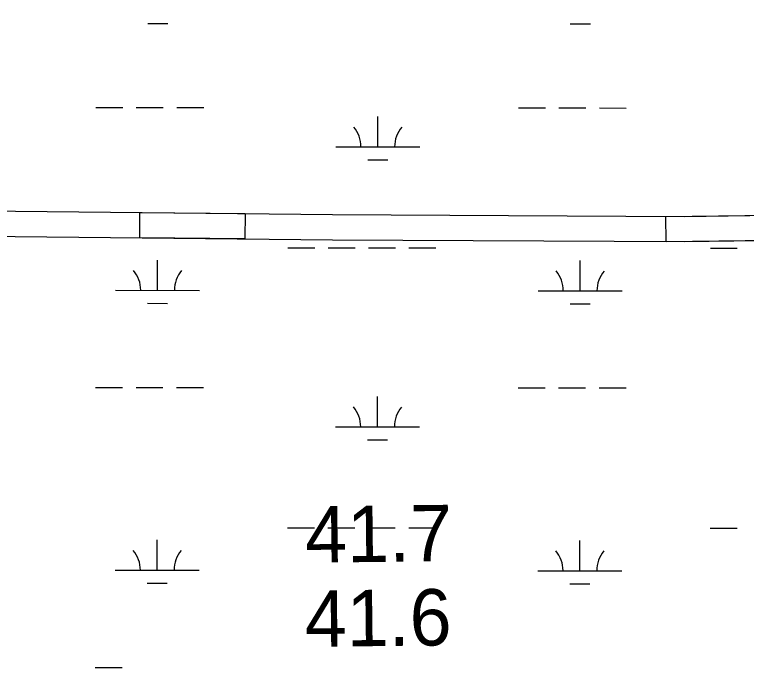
# Model space of a CAD drawing. Extents: x 3148686 to 3186545, y 916144 to 941516.
# Drawn here: x 3164337 to 3165206, y 933764 to 934539 of the extents above; entities that cross this region are included whole.
import ezdxf

# ---------------------------------------------------------------- set-up
doc = ezdxf.new("R2010")
doc.units = 0
for name, color, linetype in [('V-RIVR-RANG', 7, 'Continuous'), ('V-ROAD-CNTR', 7, 'Continuous'), ('V-WETL-SWMP', 7, 'Continuous')]:
    doc.layers.add(name, color=color, linetype=linetype)

msp = doc.modelspace()

# ---------------------------------------------------------------- linework, layer by layer
at = {"layer": 'V-ROAD-CNTR'}
for points in [[(3163359.71, 934289.29), (3163482.63, 934282.09), (3164073.39, 934278.51), (3164713.97, 934271.75), (3165132.24, 934269.66), (3165570.17, 934275.62), (3166245.62, 934279.09), (3166867.78, 934288.1), (3167164.82, 934288.69), (3167686.85, 934272.97), (3168000.91, 934271.8), (3168168.65, 934286.1), (3168244.17, 934320.97), (3168298.4, 934368), (3168350.14, 934433.57), (3168384.08, 934490.47), (3168443.51, 934622.25), (3168480.03, 934725.34), (3168496.65, 934826.01), (3168498.83, 934894.77), (3168492.36, 935008.72), (3168468.41, 935144.95), (3168439.08, 935248.42)], [(3163361.47, 934319.24), (3163483.6, 934312.08), (3164073.64, 934308.51), (3164714.2, 934301.75), (3165132.12, 934299.66), (3165235.77, 934301.07)]]:
    msp.add_lwpolyline(points, dxfattribs=at)
for points in [[(3164485.49, 934304.16), (3164610.48, 934302.84), (3164610.16, 934272.84), (3164485.17, 934274.16)], [(3165110.11, 934299.36), (3165235.1, 934301.06), (3165235.5, 934271.06), (3165110.52, 934269.36)]]:
    msp.add_lwpolyline(points, close=True, dxfattribs=at)
at = {"layer": 'V-WETL-SWMP'}
for p, q in [((3164494.63, 934528.97), (3164518.63, 934528.95)), ((3164996.54, 934528.44), (3165020.54, 934528.42)), ((3164433.12, 934429.04), (3164465.12, 934429)), ((3164481.12, 934428.99), (3164513.12, 934428.95)), ((3164529.12, 934428.94), (3164561.12, 934428.9)), ((3164935.03, 934428.51), (3164967.03, 934428.47)), ((3164983.03, 934428.46), (3165015.03, 934428.42)), ((3165031.03, 934428.41), (3165063.03, 934428.37)), ((3164767.91, 934382.25), (3164767.95, 934418.25)), ((3164717.91, 934382.31), (3164817.91, 934382.2)), ((3164755.9, 934366.84), (3164779.9, 934366.81)), ((3164660.94, 934262.3), (3164692.94, 934262.26)), ((3164708.94, 934262.25), (3164740.94, 934262.21)), ((3164756.94, 934262.19), (3164788.94, 934262.16)), ((3164804.94, 934262.14), (3164836.94, 934262.11)), ((3165162.85, 934261.77), (3165194.85, 934261.73)), ((3164506.3, 934211.72), (3164506.34, 934247.72)), ((3165008.21, 934211.19), (3165008.24, 934247.19)), ((3164456.3, 934211.77), (3164556.3, 934211.66)), ((3164958.21, 934211.24), (3165058.21, 934211.14)), ((3164494.28, 934196.3), (3164518.28, 934196.27)), ((3164996.19, 934195.77), (3165020.19, 934195.74)), ((3164432.77, 934096.36), (3164464.77, 934096.33)), ((3164480.77, 934096.31), (3164512.77, 934096.28)), ((3164528.77, 934096.26), (3164560.77, 934096.23)), ((3164934.68, 934095.83), (3164966.68, 934095.8)), ((3164982.68, 934095.78), (3165014.68, 934095.75)), ((3165030.68, 934095.73), (3165062.68, 934095.7)), ((3164767.56, 934049.58), (3164767.6, 934085.58)), ((3164717.56, 934049.63), (3164817.56, 934049.53)), ((3164755.55, 934034.16), (3164779.55, 934034.14)), ((3164660.59, 933929.62), (3164692.59, 933929.59)), ((3164708.59, 933929.57), (3164740.59, 933929.54)), ((3164756.59, 933929.52), (3164788.59, 933929.49)), ((3164804.59, 933929.47), (3164836.59, 933929.44)), ((3165162.5, 933929.09), (3165194.5, 933929.06)), ((3164505.95, 933879.04), (3164505.98, 933915.04)), ((3165007.85, 933878.51), (3165007.89, 933914.51)), ((3164455.95, 933879.09), (3164555.95, 933878.99)), ((3164957.85, 933878.57), (3165057.85, 933878.46)), ((3164493.93, 933863.62), (3164517.93, 933863.6)), ((3164995.84, 933863.09), (3165019.84, 933863.07)), ((3164432.42, 933763.69), (3164464.42, 933763.65))]:
    msp.add_line(p, q, dxfattribs=at)
for centre, start, end in [((3164712.67, 934382.79), 359.16781, 40.71147), ((3164823.16, 934382.67), 139.1678, 180.71146), ((3164451.06, 934212.25), 359.16781, 40.71147), ((3164561.54, 934212.13), 139.1678, 180.71146), ((3164952.96, 934211.72), 359.16781, 40.71147), ((3165063.45, 934211.6), 139.1678, 180.71146), ((3164712.32, 934050.11), 359.16781, 40.71147), ((3164822.81, 934050), 139.1678, 180.71146), ((3164450.7, 933879.58), 359.16781, 40.71147), ((3164561.19, 933879.46), 139.1678, 180.71146), ((3164952.61, 933879.05), 359.16781, 40.71147), ((3165063.1, 933878.93), 139.1678, 180.71146)]:
    msp.add_arc(centre, 35.25, start, end, dxfattribs=at)

# ---------------------------------------------------------------- texts
at = {"layer": 'V-RIVR-RANG'}
for s, p in [('41.7', (3164681.95, 933887.96)), ('41.6', (3164681.48, 933787.95))]:
    msp.add_text(s, height=67, rotation=0.64833, dxfattribs=at).set_placement(p)

doc.saveas('drawing.dxf')
